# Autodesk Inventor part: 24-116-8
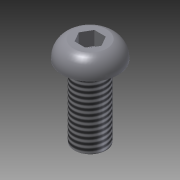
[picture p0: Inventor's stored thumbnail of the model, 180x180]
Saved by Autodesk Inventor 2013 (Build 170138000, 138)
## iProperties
Created: 2004-10
Part Number: 24-116-8
Material: Stahl (hohe Festigk., niedr. Legier.)
Document SubType Name: Modeling
Designer: Autodesk, Inc.
Manufacturer: Standard
Standards Organization: Custom
Description: SCREW, PARKER IPS, BUTTON HEAD, M8X16
Catalog Web Link: http://www.parker.com/ead/cm1.asp?cmid=809
Vendor: PARKER IPS
Mass: 10.8823 g
Surface Area: 9.37524 cm^2
Volume: 1.38805 cm^3
Density: 7.84 g/cm^3
CAGE: 1LJX3
Dept. ID: Product Design
Description #2: ---
Finish #1: ---
Finish #2: ---
Material ID: ---
Project Number: ---
Author: Autodesk, Inc.
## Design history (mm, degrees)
derived "2X-YYY-ZZ IPS Screws.ipt"
body "Solid1"
tag "TaggingFeature2"
feature "Solid1::2X-YYY-ZZ IPS Screws.ipt" dims "ScaleForDerivedMember" = 10
